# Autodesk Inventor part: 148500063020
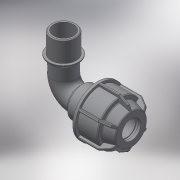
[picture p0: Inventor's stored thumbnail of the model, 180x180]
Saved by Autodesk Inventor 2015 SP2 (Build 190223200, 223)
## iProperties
Created: 2017-08
Part Number: 148500063020
Material: Generic
Description: PLASSON L.14 90° ELBOW MALE ADAPTOR (SILVER) 63-2"
Document SubType Name: Modeling
Designer: KIM
Density: 1 g/cm^3
Appearance: Default
Author: KIM
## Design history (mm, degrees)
derived "148500.ipt"
feature "Solid1::148500.ipt"
feature "Solid2::148500.ipt"
tag "TaggingFeature1"
body "Solid1"
body "Solid2"
other parameters: "d1" = 63, "d2" = 82, "d4" = 15 deg, "d5" = 54.12, "d6" = 17.8596, "d10" = 106, "d16" = 64.26, "d17" = 4.1, "d22" = 100.8, "d24" = 4.1, "d25" = 95.4, "d26" = 79.5, "d27" = 4.1, "d28" = 135 deg, "d29" = 2.46, "d31" = 3.15, "d46" = 150 deg, "d49" = 5.3, "d50" = 0, "d58" = 1.89, "d61" = 360 deg, "d63" = 50.4, "d94" = 84, "d96" = 65.5754, "d97" = 26, "d98" = 47.6912, "d99" = 55.73909, "d100" = 135 deg, "d108" = 3.15, "d112" = 33.8, "d113" = 119, "d114" = 90.2, "d115" = 55.73909, "d116" = 45 deg, "d117" = 0, "d118" = 0, "d119" = 59.614, "d120" = 26, "d121" = 71.5368, "d122" = 27.3, "d123" = 1, "d_" = 63, "R_" = 59.614, "E_" = 106, "A_" = 119, "l_" = 82, "l_2" = 26, "A_1" = 84
